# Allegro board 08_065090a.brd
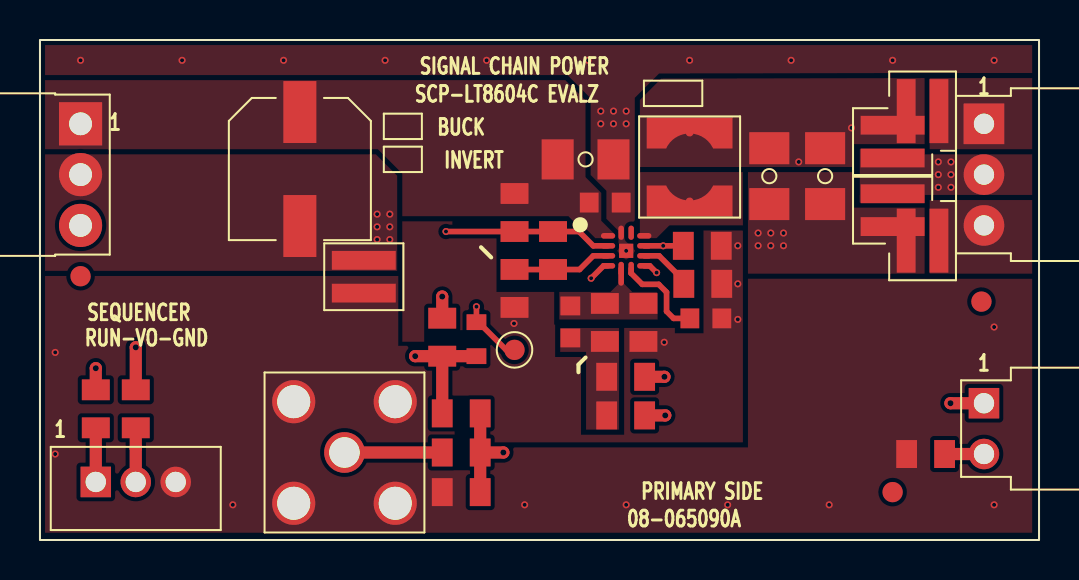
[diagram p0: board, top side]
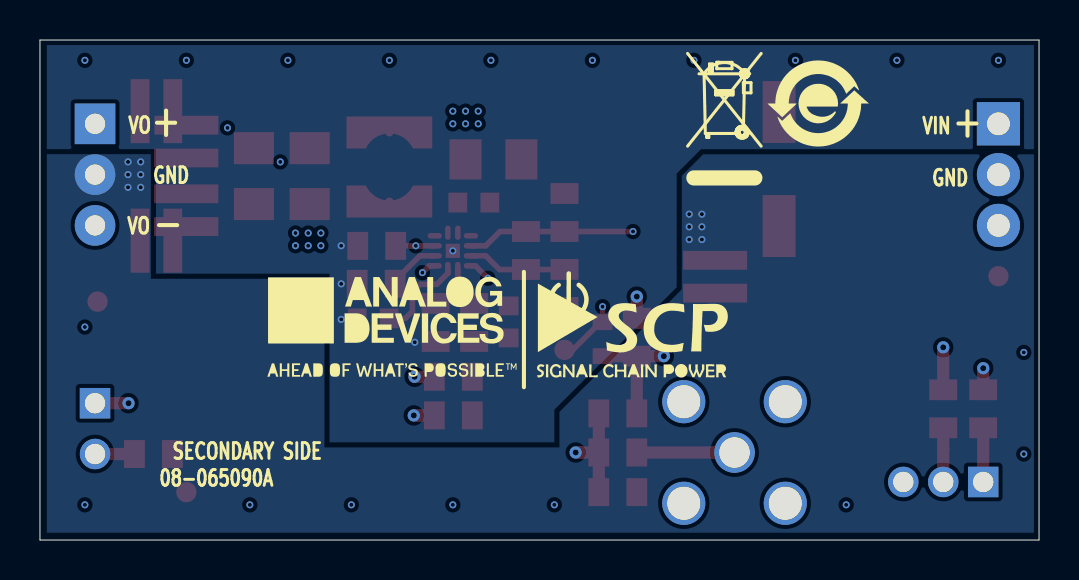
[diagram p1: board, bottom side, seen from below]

Outline 50 x 25 mm; copper layers: TOP, L2_GND, L3_SIGNAL, BOTTOM. Coordinates in mm from the lower left corner of the outline.
Outline path: 0,25 50,25 50,0 0,0 0,25

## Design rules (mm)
constraint set DEFAULT: min track width 0.254

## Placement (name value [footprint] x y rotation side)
C1  22uF  [CPLSMSQ260H315]  13.01 18.55 270 top
C2  1uF  [C1206H71]  27.3 19.03 0 top
C3  0.1uF  [C0603]  28.29 16.87 0 top
C5  10pF  [C0603]  26.54 10.9 270 top
C6  10uF  [C1206H71]  39.29 18.19 270 top
C8  0.01uF  [C0603]  33.32 11.08 0 top
C9  4.7uF  [C1206H71]  36.5 18.19 270 top
INPUT  PBC03SBAN  [CNTHMHDRRA1X3L300W100H145]  2.03 20.81 270 top
J1  5-1814832-2  [CNTYCO1814832]  15.24 4.38 0 top
L1  33UH  [LSMSQ150H71]  32.51 18.65 90 top
NOREF  -  []  25.51 46.03 0 top
NOREF#2  -  []  95.95 95.7 0 top
NOREF#3  -  []  0 0 0 top
NOREF#4  -  []  0 25 0 top
NOREF#5  -  []  50 25 180 top
NOREF#6  -  []  -197.25 -222.03 0 top
NOREF#7  -  []  -131.19 155.48 0 top
NOREF#8  -  []  -197.25 -222.03 0 top
NOREF#9  -  []  50 0 90 top
NOREF#10  -  []  50 0 90 top
NOREF#11  -  [unnamed#2]  42.67 2.39 0 top
NOREF#12  -  []  2.03 20.81 0 top
NOREF#13  -  []  0 25 270 top
NOREF#14  -  [unnamed#2]  47.12 11.92 0 top
NOREF#15  -  [unnamed#2]  2.03 13.19 0 top
NOREF#16  -  []  90.79 32.31 0 top
NOREF#17  -  []  -197.25 -222.03 0 top
NOREF#18  -  []  0 0 0 top
NOREF#19  -  []  0 25 0 top
NOREF#20  -  []  -137.31 -48.38 0 top
NOREF#21  -  []  2.03 20.81 0 top
NOREF#22  -  []  50 25 0 top
NOREF#23  -  []  0 0 0 top
NOREF#24  -  []  32.67 10.63 180 bottom
NOREF#25  -  []  11.05 21.82 180 bottom
NOREF#26  -  []  15.95 17.79 180 bottom
NOREF#27  -  []  20.32 10.78 180 bottom
NOREF#28  -  []  17.55 11.26 180 bottom
OUTPUT  PPPC031LGBN-RC  [CNHDRRA1X3H108]  47.24 20.81 270 top
P1  53253-0370  [CNTHMHDR1X3L315W144H224]  2.79 2.9 0 top
R1  1MEG  [R0805]  23.75 16.37 270 top
R2  18.2K  [R0805]  33.17 12.81 0 top
R3  49.9K  [R0603]  21.84 10.04 270 top
R4  1MEG  [R0805]  28.27 10.88 270 top
R5  187K  [R0805]  30.2 10.88 270 top
R6  TBD0805  [R0805]  25.68 14.47 270 top
R7  TBD0805  [R0805]  23.75 12.58 270 top
R8  0  [R0805]  29.31 8.16 180 top
R9  0  [R0805]  20.13 10.14 270 top
R10  TBD0805  [R0805]  33.15 14.71 0 top
R11  TBD0805  [R0805]  2.79 6.56 90 top
R12  TBD0805  [R0805]  4.8 6.56 90 top
R13  TBD0805  [R0805]  44.32 4.3 0 top
R14  0  [R0612]  16.21 13.16 270 top
R15  0  [R0612]  42.67 16.49 90 top
R16  0  [R0612]  44.17 21.44 0 top
R17  0  [R0612]  42.67 19.92 270 top
R18  0  [R0612]  44.17 14.97 0 top
R19  TBD0805  [R0805]  29.31 6.23 0 top
R20  TBD0805  [R0805]  21.08 2.39 180 top
R21  TBD0805  [R0805]  21.08 6.33 0 top
R22  TBD0805  [R0805]  21.08 4.38 0 top
TP1  TESTPAD  [TPSMC40]  23.75 9.51 0 top
U1  LT8604CAV#TRMPBF  [QFN12_2X2_PAD0_7X0_7]  29.34 14.46 270 top
VIOC  PPPC021LGBN-RC  [CNTHFHDRRA1X2L220W335H108]  47.24 6.84 270 top

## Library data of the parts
C1 = CAPP: Tolerance: 20; User Part Number: UPN; alternate symbols: (); part number: CAPP_SM-22UF,63V,20,E034289,CPLSMSQ260H315; tolerance: 20
C2 = CAP: Tolerance: 10; User Part Number: UPN; alternate symbols: (); part number: CAP_SM-1UF,50V,10,E031061,C1206H71; tolerance: 10
C3 = CAP: User Part Number: UPN; Tolerance: 10; alternate symbols: (C0603L); part number: CAP_SM-0.1UF,50V,10,E038267,C0603; tolerance: 10
C5 = CAP: User Part Number: UPN; Tolerance: 5; alternate symbols: (C0603L); part number: CAP_SM-10PF,50V,5,E034361,C0603; tolerance: 5
C6 = CAP: Tolerance: 20; User Part Number: UPN; alternate symbols: (); part number: CAP_SM-10UF,50V,20,E035601,C1206H71; tolerance: 20
C8 = CAP: User Part Number: UPN; Tolerance: 10; alternate symbols: (C0603L); part number: CAP_SM-0.01UF,50V,10,E018587,C0603; tolerance: 10
C9 = CAP: Tolerance: 10; User Part Number: UPN; alternate symbols: (); part number: CAP_SM-4.7UF,50V,10,E038262,C1206H71; tolerance: 10
INPUT = CN3P: Tolerance: N/A; User Part Number: UPN; alternate symbols: (CNTHMHDRRA1X3L300W100H145_SCP); part number: CN3P_TH-PBC03SBAN,E034137,CNTHMHDRRA1X3L300W100H145; tolerance: N/A
J1 = CNBNC5P: Tolerance: N/A; User Part Number: UPN; alternate symbols: (); part number: CNBNC5P_TH-5-1814832-2,E010606,CNTYCO1814832; tolerance: N/A
L1 = IND: User Part Number: UPN; Tolerance: 30; alternate symbols: (); part number: IND_SM-33UH,30,E040015,LSMSQ150H71; tolerance: 30
OUTPUT = CN3P: User Part Number: UPN; Tolerance: N/A; alternate symbols: (CNHDRRA1X3H108_SCP); part number: CN3P_TH-PPPC031LGBN-RC,E034111,CNHDRRA1X3H108; tolerance: N/A
P1 = CN3P: Tolerance: N/A; User Part Number: UPN; alternate symbols: (); part number: CN3P_TH-53253-0370,E033940,CNTHMHDR1X3L315W144H224; tolerance: N/A
R1 = RES: User Part Number: UPN; Tolerance: 5; alternate symbols: (R0805L); part number: RES_SM-1MEG,E033749,1/8W,5,R0805; tolerance: 5
R2 = RES: User Part Number: UPN; Tolerance: 1; alternate symbols: (R0805L); part number: RES_SM-18.2K,E020752,1/8W,1,R0805; tolerance: 1
R3 = RES: User Part Number: UPN; Tolerance: 1; alternate symbols: (R0603L); part number: RES_SM-49.9K,E015342,1/10W,1,R0603; tolerance: 1
R4 = RES: User Part Number: UPN; Tolerance: 1; alternate symbols: (R0805L); part number: RES_SM-1MEG,E003518,1/8W,1,R0805; tolerance: 1
R5 = RES: User Part Number: UPN; Tolerance: 1; alternate symbols: (R0805L); part number: RES_SM-187K,E015129,1/8W,1,R0805; tolerance: 1
R6 R7 R10-R13 R19-R22 = RES: User Part Number: UPN; alternate symbols: (R0805L); part number: RES_SM-TBD0805,E004051,TBD0805,TBD0805,R0805
R8 R9 = RES: User Part Number: UPN; Tolerance: JUMPER; alternate symbols: (R0805L); part number: RES_SM-0,E030875,1/8W,JUMPER,R0805; tolerance: JUMPER
R14-R18 = RES: User Part Number: UPN; Tolerance: N/A; alternate symbols: (R0612L); part number: RES_SM-0,E034651,3/4W,N/A,R0612; tolerance: N/A
TP1 = NCTESTPAD: Tolerance: N/A; User Part Number: UPN; alternate symbols: (); part number: NCTESTPAD_SM-TESTPAD,E019801,TPSMC40; tolerance: N/A
U1 = ADLT8604: User Part Number: UPN; Tolerance: N/A; alternate symbols: (); part number: ADLT8604_SM-LT8604CAV#TRMPBF,E055399,QFN12_2X2_PAD0_7X0_7; tolerance: N/A
VIOC = CN2P: Tolerance: N/A; User Part Number: UPN; alternate symbols: (CNTHFHDRRA1X2L220W335H108_SCP); part number: CN2P_TH-PPPC021LGBN-RC,E034113,CNTHFHDRRA1X2L220W335H108; tolerance: N/A

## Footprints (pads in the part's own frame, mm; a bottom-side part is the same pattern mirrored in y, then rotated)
C0603
  rect 0.94x0.991 smd: 1(-0.8,0) 2(0.8,0)
C1206H71
  rect 1.6x2.007 smd: 1(-1.397,0) 2(1.397,0)
CNHDRRA1X3H108
  rect 2.032x2.032 hole 1.016: 1(0,0)
  round 2.032 hole 1.016: 2(2.54,0) 3(5.08,0)
CNTHFHDRRA1X2L220W335H108
  rect 1.524x1.524 hole 1.016: 1(0,0)
  round 1.524 hole 1.016: 2(2.54,0)
CNTHMHDR1X3L315W144H224
  rect 1.524x1.524 hole 1.016: 1(0,0)
  round 1.524 hole 1.016: 2(2,0) 3(4,0)
CNTHMHDRRA1X3L300W100H145
  rect 2.159x2.159 hole 1.143: 1(0,0)
  round 2.159 hole 1.143: 2(2.54,0) 3(5.08,0)
CNTYCO1814832
  round 2.032 hole 1.524: 1(0,0)
  round 2.159 hole 1.651: 2(-2.54,2.54) 3(2.54,2.54) 4(2.54,-2.54) 5(-2.54,-2.54)
CPLSMSQ260H315
  rect 3.099x1.651 smd: N(2.85,0) P(-2.85,0)
LSMSQ150H71
  custom 0.4x0.4 smd: 1(-1.725,0) 2(1.725,0)
QFN12_2X2_PAD0_7X0_7
  oval 0.279x0.711 smd: 1(-0.75,-0.906) 2(-0.25,-0.906) 3(0.25,-0.906) 4(0.75,-0.906) 7(0.75,0.906) 8(0.25,0.906) 9(-0.25,0.906) 10(-0.75,0.906)
  oval 0.711x0.279 smd: 5(0.906,-0.25) 6(0.906,0.25) 11(-0.906,0.25) 12(-0.906,-0.25)
  rect 0.711x0.711 smd: PAD(0,0)
R0603
  rect 0.787x0.991 smd: 1(-0.85,0) 2(0.85,0)
R0612
  rect 0.94x3.2 smd: 1(-0.82,0) 2(0.82,0)
R0805
  rect 1.041x1.397 smd: 1(-0.95,0) 2(0.95,0)
TPSMC40
  round 1.016 smd: 1(0,0)
unnamed#2
  round 1.016 smd: (0,0)

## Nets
GND: C1.N(N2) INPUT.2 OUTPUT.2 R14.1 R15.2(N2) R17.2(N2)
RUN: P1.1 R11.1
SYNC: R20.1 R21.2(N2) R22.2(N2) U1.7
UNNAMED_2_ADLT8604_I35_BIAS: R9.1 R10.1 U1.9
UNNAMED_2_ADLT8604_I35_FB: C5.1 R4.1 R5.1 U1.5
UNNAMED_2_ADLT8604_I35_HYST: R6.2(N2) R7.1 U1.3
UNNAMED_2_ADLT8604_I35_PG: R3.1 TP1.1(N1) U1.4
UNNAMED_2_ADLT8604_I35_RT: R2.1 U1.8
UNNAMED_2_ADLT8604_I35_SW: L1.1 U1.10
UNNAMED_2_ADLT8604_I35_TR: C8.1 U1.6
UNNAMED_2_CAP_I26_N1: C6.1 C9.1 L1.2(N2) R3.2(N2) R8.1 R9.2(N2) R16.1 R17.1 R21.1
UNNAMED_2_CN2P_I32_N2: R13.2(N2) VIOC.2(N2)
UNNAMED_2_CN3P_I1_N2: P1.2 R12.1
UNNAMED_2_CNBNC5P_I37_CNTR: J1.1 R22.1
UNNAMED_2_RES_I10_N2: R1.2(N2) R6.1 R11.2(N2) U1.2
UNNAMED_2_RES_I17_N2: C5.2(N2) R4.2(N2) R8.2(N2) R19.1
V+: C1.P C2.1 C3.1 INPUT.1 R1.1 U1.1(VIN)
VIOC: R19.2(N2) VIOC.1
VNEG: C2.2(N2) C3.2(N2) C6.2(N2) C8.2(N2) C9.2(N2) J1.2 J1.3 J1.4 J1.5(SH4) P1.3(N3) R2.2(N2) R5.2(N2) R7.2(N2) R10.2(N2) R13.1 R14.2(N2) R15.1 R18.1 R20.2(N2) U1.12 U1.PAD
VO+: OUTPUT.1 R12.2(N2) R16.2(N2)
VO-: OUTPUT.3(N3) R18.2(N2)

Pads without a net: INPUT 3; U1 11

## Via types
v1: diameter 0.61, hole 0.305, TOP to BOTTOM, 8 vias
v2: diameter 0.356, hole 0.203, TOP to BOTTOM, 56 vias

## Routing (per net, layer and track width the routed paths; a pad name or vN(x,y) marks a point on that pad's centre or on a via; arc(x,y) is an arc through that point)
GND:
  vias: v2(16.87,16.29) v2(16.87,15.66) v2(16.87,15.02) v2(17.51,16.29) v2(17.51,15.66) v2(17.51,15.02) v2(44.96,18.9) v2(44.96,18.27) v2(44.96,17.63) v2(45.59,18.9) v2(45.59,18.27) v2(45.59,17.63)
RUN: length 2.7
  TOP w0.61: R11.1 P1.1
SYNC: length 18
  TOP w0.279: v2(30.86,13.37) 30.52,13.71 U1.7
  TOP w0.61: R22.2 R21.2 ; R22.2 R20.1 ; R22.2 v1(23.19,4.38)
  L3_SIGNAL w0.279: v1(23.19,4.38) 23.19,5.7 v2(30.86,13.37)
UNNAMED_2_ADLT8604_I35_BIAS: length 15.4
  TOP w0.279: U1.9 v2(31.19,14.71) R10.1
  TOP w0.61: R9.1 v1(20.13,12.17)
  L3_SIGNAL w0.279: v1(20.13,12.17) 23.04,15.08 30.82,15.08 v2(31.19,14.71)
UNNAMED_2_ADLT8604_I35_FB: length 0.7
  TOP w0.279: U1.5 29.09,12.86
UNNAMED_2_ADLT8604_I35_HYST: length 5
  TOP w0.279: U1.3 27.69,14.21 27.01,13.52 R6.2 23.75,13.52 R7.1
UNNAMED_2_ADLT8604_I35_PG: length 10.7
  TOP w0.279: U1.4 28.21,13.71 v2(27.58,13.09) ; v2(21.84,11.67) R3.1 21.95,10.89 23.33,9.51 TP1.1
  L3_SIGNAL w0.279: v2(27.58,13.09) 23.27,13.09 v2(21.84,11.67)
UNNAMED_2_ADLT8604_I35_RT: length 2.7
  TOP w0.279: U1.8 30.98,14.21 32.22,12.97 R2.1
UNNAMED_2_ADLT8604_I35_TR: length 4.6
  TOP w0.279: U1.6 29.59,13.34 30.14,12.78 30.97,12.78 31.36,12.39 31.36,11.43 31.71,11.08 C8.1
UNNAMED_2_CAP_I26_N1: length 51.3
  TOP w0.61: R21.1 R9.2 ; R9.2 v1(18.78,9.19) ; R9.2 R3.2 ; R8.1 v1(31.25,8.16)
  L3_SIGNAL w0.279: v2(40.61,20.61) 39.85,19.84 26.34,19.84 18.78,12.28 v1(18.78,9.19) ; v1(31.25,8.16) 34.92,8.16 38.35,11.59 38.35,18.52 v2(37.97,18.9)
UNNAMED_2_CN2P_I32_N2: length 2
  TOP w0.61: VIOC.2 R13.2
UNNAMED_2_CN3P_I1_N2: length 2.7
  TOP w0.61: R12.1 4.8,4.58 4.79,4.58 P1.2
UNNAMED_2_CNBNC5P_I37_CNTR: length 4.9
  TOP w0.61: J1.1 R22.1
UNNAMED_2_RES_I10_N2: length 29.8
  TOP w0.279: v2(20.32,15.42) R1.2 R6.1 26.97,15.42 27.69,14.71 U1.2
  TOP w0.61: R11.2 v1(2.79,8.59)
  L3_SIGNAL w0.279: v1(2.79,8.59) 7.77,8.59 11.43,12.25 17.14,12.25 v2(20.32,15.42)
VIOC: length 17.2
  TOP w0.61: v1(31.29,6.23) R19.2 ; VIOC.1 v1(45.57,6.84)
  L3_SIGNAL w0.279: v1(31.29,6.23) 44.96,6.23 v1(45.57,6.84)
VNEG:
  vias: v2(0.76,9.38) v2(0.76,4.3) v2(2.03,23.98) v2(7.11,23.98) v2(9.65,1.76) v2(12.19,23.98) v2(17.27,23.98) v2(22.35,23.98) v2(23.72,10.83) v2(24.26,1.76) v2(27.43,23.98) v2(28.07,21.44) v2(28.07,20.81) v2(28.7,21.44) v2(28.7,20.81) v2(29.34,21.44) v2(29.34,20.81) v2(29.34,14.46) v2(29.34,1.76) v2(31.24,9.89) v2(32.51,23.98) v2(34.42,1.76) v2(34.92,14.71) v2(34.92,12.81) v2(34.92,11.03) v2(35.94,15.35) v2(35.94,14.71) v2(36.58,15.35) v2(36.58,14.71) v2(37.21,15.35) v2(37.21,14.71) v2(37.59,23.98) v2(39.5,1.76) v2(42.67,23.98) v2(47.75,23.98) v2(47.75,10.65) v2(47.75,1.76)
VO+: length 50.6
  TOP w0.61: R12.2 v1(4.8,9.63)
  L3_SIGNAL w0.279: v1(4.8,9.63) 17.67,22.51 45.54,22.51 OUTPUT.1

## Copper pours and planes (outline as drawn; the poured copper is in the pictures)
GND on TOP: 41.03,17.25 41.02,17.25 41.02,16.87 44.2,16.87 44.2,17.25 49.66,17.25 49.66,19.29 44.2,19.29 44.2,19.54 41.03,19.54
GND on TOP: 0.25,19.29 0.25,13.46 17.88,13.46 17.88,18.21 16.8,19.29
GND on BOTTOM: 44.45,19.29 49.66,19.29 49.66,0.36 0.25,0.36 0.25,19.29 1.26,19.29 0.89,18.84 0.76,18.27 2.03,16.99 3.31,18.27 3.18,18.84 2.8,19.29 16.8,19.29 17.88,18.21 17.88,12.53 24,6.41 24,4.63 35.76,4.63 35.76,13.06 44.45,13.06
UNNAMED_2_ADLT8604_I35_FB on TOP: 25.99,12.4 25.99,11.02 30.91,11.02 30.91,12.4 29.64,12.4 29.21,12.83 29.21,13.47 28.96,13.47 28.96,12.81 28.55,12.4
UNNAMED_2_ADLT8604_I35_SW on TOP: 30.02,18.4 30.02,15.09 30.86,15.09 31.5,15.73 35.18,15.73 35.18,18.4
UNNAMED_2_CAP_I26_N1 on TOP: 31.09,23.07 44.27,23.1 44.27,19.79 40.64,19.79 40.64,18.65 30.02,18.65 30.02,22
UNNAMED_2_RES_I17_N2 on TOP: 26.04,10.6 26.04,9.4 27.33,9.4 27.33,5.52 28.98,5.52 28.98,10.6
V+ on TOP: 0.25,22.99 26.29,22.99 27.3,21.98 27.3,18.14 28.09,17.35 28.09,15.96 28.7,15.35 28.7,15.09 27.53,15.09 26.45,16.19 18.13,16.19 18.13,18.32 16.91,19.54 0.25,19.54
VNEG on TOP: 0.25,24.75 49.66,24.75 49.66,0.36 0.25,0.36 ; 7 cut-outs
VNEG on BOTTOM: 10.41,24.75 49.66,24.75 49.66,19.54 44.2,19.54 44.2,13.32 35.51,13.32 35.51,4.88 24.26,4.88 24.25,6.51 18.14,12.63 18.14,18.32 16.92,19.54 0.25,19.54 0.25,24.75 ; 12 cut-outs
VNEG on L2_GND: 0.25,24.75 49.66,24.75 49.66,0.36 0.27,0.36 ; 5 cut-outs
VNEG on L3_SIGNAL: 0.25,24.75 49.78,24.75 49.78,0.24 0.25,0.24 ; 26 cut-outs
VO+ on TOP: 44.49,23.1 44.49,19.54 49.66,19.54 49.66,23.1
VO- on TOP: 44.53,17 44.53,13.32 49.66,13.32 49.66,17

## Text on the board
Ref Des/Silkscreen Bottom: GND | VIN | SECONDARY SIDE | 08-065090A | VO | + | -
User.Comments: 4.    RoHS COMPLIANCE: ASSEMBLY VENDOR SHOULD ASSURE COMPLIANCE | WITH LEAD-FREE AND RoHS PCB ASSEMBLY STANDARDS (EU RoHS | DIRECTIVE 2002/95/EC).
Ref Des/Silkscreen Top: SEQUENCER | RUN-VO-GND | BUCK | INVERT | SCP-LT8604C EVALZ | SIGNAL CHAIN POWER | 08-065090A | PRIMARY SIDE
ROOT_NUMBER: 065090
DIMENSION: REF | DIA MAX | SEE FAB NOTES 15
PAGE_OUTLINE: N/A | A.CAUILAN | K.JABATAN | L EVANGELIO | A.SERQUINA | 05DEC18 | 17AUG20 | 03SEP20 | A | SCP-LT8604 EVALZ | EVALUATION BOARD | -065090
User.15: ROHS COMPLIANCE NOTE:  (Required for Customer Boards) Add to top of MATERIALS | ENIG (Electroless Nickel/Immersion Gold) | PER IPC-4552 LATEST REVISION | HOMOGENOUS MATERIALS IN THIS BOARD SHALL BE COMPLIANT | THE EU RoHS DIRECTIVE 2002/95/EC | INTERNAL LAYERS 1 OZ. COPPER. | 15.    THRU VIAS TO BE FILLED WITH SOLDERMASK. | 0.0035"
User.17: L2 GND | 08-      -07
User.18: L3 SIGNAL | 08-      -08
User.23: 1 | A
User.27: 2 | A
User.45: 2 | FIGURE | SIZE | 8.0 | 12.0 | 40.0 | 45.0 | 60.0 | 65.0 | PLATED | FINISHED HOLES IN MILS | ALL UNITS ARE IN MILS | QTY | 56 | 8 | 3 | 1 | 4 | TOLERANCE/NOTES | EVALUATION BOARD | A
